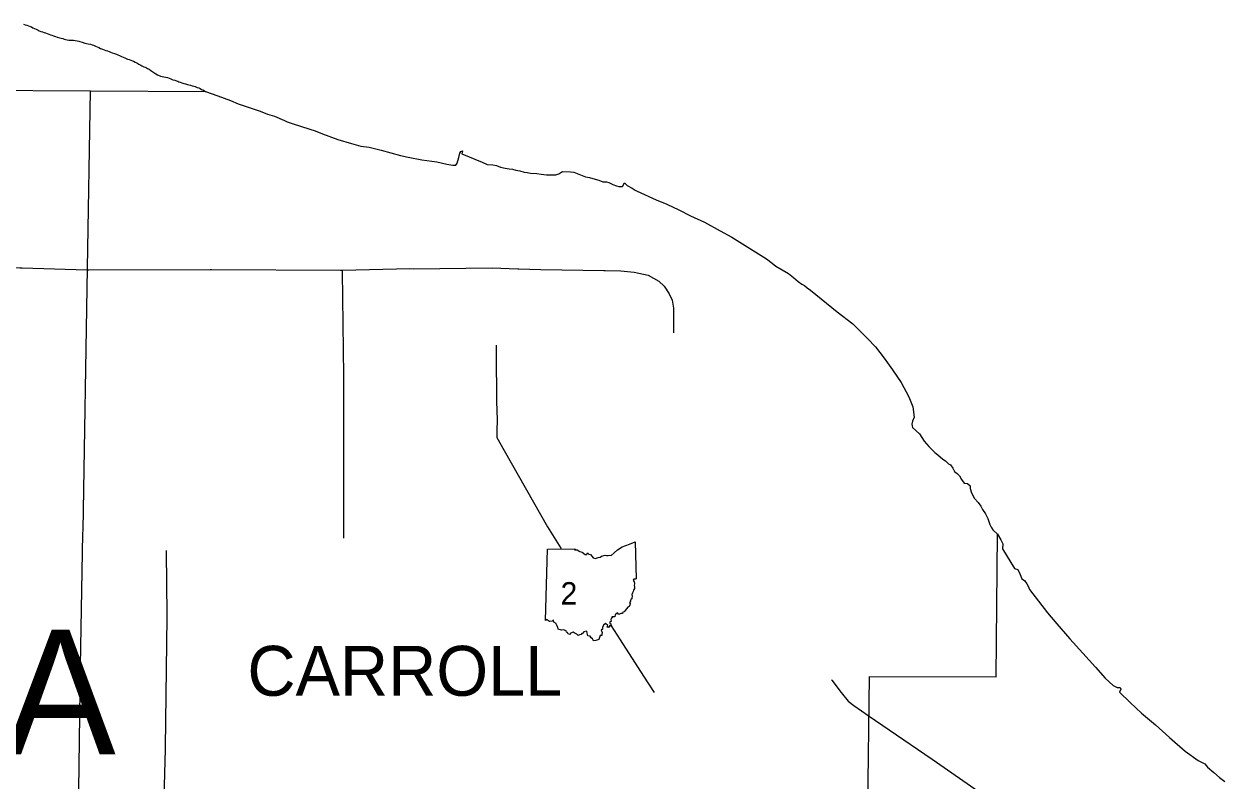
# Model space of a CAD drawing. Extents: x -232 to 448, y 619 to 1059.
# Drawn here: x 271.78 to 321.22, y 890 to 921.13 of the extents above; entities that cross this region are included whole.
import ezdxf

# ---------------------------------------------------------------- set-up
doc = ezdxf.new("R2010")
doc.units = 0
doc.layers.add('Default', color=7, linetype='Continuous')

msp = doc.modelspace()

# ---------------------------------------------------------------- linework, layer by layer
at = {"layer": 'Default'}
msp.add_line((293.244, 896.597), (293.326, 899.525), dxfattribs=at)
msp.add_line((293.244, 896.597), (293.326, 899.525), dxfattribs=at)
for points in [[(271.758, 921.129), (271.835, 921.103), (271.898, 921.082), (271.962, 921.058), (272.035, 921.032), (272.094, 921.008), (272.147, 920.978), (272.218, 920.946), (272.285, 920.92), (272.358, 920.876), (272.411, 920.85), (272.47, 920.829), (272.546, 920.802), (272.613, 920.787), (272.666, 920.767), (272.739, 920.735), (272.8, 920.709), (272.87, 920.686), (272.923, 920.666), (273, 920.642), (273.074, 920.622), (273.147, 920.596), (273.2, 920.579), (273.253, 920.563), (273.318, 920.546), (273.377, 920.528), (273.433, 920.513), (273.496, 920.499), (273.555, 920.48), (273.622, 920.468), (273.694, 920.463), (273.754, 920.462), (273.823, 920.462), (273.891, 920.457), (273.971, 920.441), (274.032, 920.424), (274.085, 920.408), (274.169, 920.382), (274.283, 920.347), (274.356, 920.329), (274.426, 920.314), (274.516, 920.302), (274.587, 920.28), (274.638, 920.257), (274.724, 920.222), (274.789, 920.194), (274.862, 920.16), (274.935, 920.129), (275.013, 920.099), (275.082, 920.071), (275.153, 920.043), (275.216, 920.024), (275.282, 920.002), (275.345, 919.976), (275.414, 919.946), (275.502, 919.918), (275.587, 919.887), (275.644, 919.862), (275.713, 919.831), (275.801, 919.789), (275.87, 919.761), (275.933, 919.739), (275.983, 919.714), (276.039, 919.691), (276.111, 919.672), (276.177, 919.649), (276.25, 919.619), (276.289, 919.596), (276.355, 919.56), (276.428, 919.527), (276.503, 919.474), (276.589, 919.431), (276.638, 919.408), (276.717, 919.375), (276.767, 919.352), (276.819, 919.323), (276.869, 919.303), (276.902, 919.283), (276.931, 919.267), (276.997, 919.214), (277.037, 919.184), (277.205, 919.075)], [(277.205, 919.075), (277.273, 919.039), (277.403, 918.988), (277.475, 918.967), (277.539, 918.962), (277.609, 918.949), (277.684, 918.928), (277.756, 918.898), (277.825, 918.871), (277.911, 918.841), (277.985, 918.818), (278.055, 918.794), (278.108, 918.773), (278.161, 918.754), (278.214, 918.735), (278.284, 918.712), (278.358, 918.688), (278.435, 918.663), (278.505, 918.648), (278.565, 918.631), (278.638, 918.616), (278.704, 918.59), (278.776, 918.571), (278.831, 918.554), (278.909, 918.524), (278.972, 918.499), (279.027, 918.474), (279.084, 918.442), (279.14, 918.417), (279.258, 918.348)], [(241.621, 918.197), (255.575, 918.495), (274.524, 918.377)], [(273.973, 884.01), (273.991, 886.54), (274.111, 894.733), (274.2, 900.175), (274.21, 900.311), (274.401, 911.082), (274.524, 918.377)], [(274.524, 918.377), (279.258, 918.348)], [(279.258, 918.348), (279.753, 918.179), (280.28, 917.98), (280.591, 917.854), (280.921, 917.736), (281.212, 917.643), (281.507, 917.542), (281.808, 917.42), (282.091, 917.334), (282.505, 917.167), (282.619, 917.108), (282.82, 917.045), (283.544, 916.807), (283.763, 916.74), (284.068, 916.608), (284.693, 916.384), (285.261, 916.222), (285.643, 916.111), (285.992, 916.059), (286.48, 915.947), (287.272, 915.728), (287.592, 915.655), (288.159, 915.549), (288.77, 915.456), (289.184, 915.363), (289.435, 915.323), (289.552, 915.329), (289.605, 915.4), (289.68, 915.645), (289.726, 915.821), (289.758, 915.891), (289.833, 915.912), (289.8, 915.789), (290.639, 915.444)], [(290.639, 915.444), (290.85, 915.356), (291.086, 915.332), (291.23, 915.311), (291.398, 915.24), (291.589, 915.196), (291.753, 915.168), (291.895, 915.162), (292.024, 915.122), (292.185, 915.098), (292.365, 915.042), (292.495, 915.017), (292.624, 915), (292.889, 914.98), (293.068, 914.96), (293.286, 914.922), (293.417, 914.93), (293.533, 914.927), (293.676, 914.923), (293.792, 914.963), (293.876, 915.027), (293.944, 915.066), (294.275, 915.056), (294.411, 915.039), (294.887, 914.845), (295.059, 914.813), (295.289, 914.746), (295.448, 914.704), (295.61, 914.636), (295.76, 914.635), (295.858, 914.616), (296.016, 914.527), (296.164, 914.47), (296.271, 914.451), (296.326, 914.447), (296.415, 914.442), (296.504, 914.594), (296.602, 914.483), (296.811, 914.377), (296.94, 914.296), (297.025, 914.252), (297.804, 913.905), (298.243, 913.719), (298.736, 913.484), (299.214, 913.247), (299.786, 912.979), (300.432, 912.622), (300.915, 912.36), (301.46, 912.015), (301.8, 911.808), (302.12, 911.615), (302.348, 911.476), (302.579, 911.289), (302.733, 911.171), (303.246, 910.872), (303.449, 910.701), (303.641, 910.539), (303.795, 910.433), (303.912, 910.379), (304.021, 910.282), (304.16, 910.187), (305.252, 909.296), (305.898, 908.792), (306.504, 908.192), (306.825, 907.857), (307.183, 907.392), (307.528, 906.903), (307.886, 906.39), (308.2, 905.791), (308.373, 905.379), (308.423, 904.954), (308.357, 904.798), (308.329, 904.668), (308.36, 904.539), (308.642, 904.272), (308.832, 903.97), (309.023, 903.757), (309.272, 903.507), (309.395, 903.407), (309.598, 903.233), (309.709, 903.167), (309.779, 903.095), (309.838, 903.045), (309.922, 902.997), (310.012, 902.867), (310.087, 902.72), (310.194, 902.646), (310.288, 902.542), (310.368, 902.396), (310.486, 902.239), (310.614, 902.234), (310.731, 902.137), (310.724, 902.03), (310.779, 901.852), (310.903, 901.609), (311.059, 901.447), (311.163, 901.305), (311.237, 901.166), (311.355, 900.978), (311.455, 900.788), (311.53, 900.541)], [(263.548, 911.236), (268.802, 911.127), (268.896, 911.125), (271.605, 911.101), (271.711, 911.1), (274.364, 911.019), (274.454, 911.016), (279.438, 911.028), (279.505, 911.028), (284.814, 911.012), (284.814, 911.012), (284.826, 911.012)], [(284.826, 911.012), (284.886, 911.012), (287.657, 911.071), (287.815, 911.065), (291.047, 911.098), (292.102, 911.066)], [(292.102, 911.066), (292.156, 911.064)], [(292.156, 911.064), (293.055, 911.037), (294.784, 911.004), (295.65, 910.995), (295.706, 910.995)], [(284.945, 902.04), (284.946, 906.577), (284.946, 906.664), (284.888, 910.943), (284.888, 910.943), (284.886, 911.012)], [(295.706, 910.995), (296.348, 910.983), (296.899, 910.919), (297.475, 910.802), (297.911, 910.557), (298.125, 910.345), (298.337, 910.034), (298.464, 909.77), (298.512, 909.437), (298.52, 908.477), (298.52, 908.432)], [(291.219, 907.916), (291.22, 907.581), (291.232, 905.619), (291.258, 904.84), (291.245, 904.416), (291.245, 904.128), (291.544, 903.59), (293.334, 900.444), (293.874, 899.568), (293.894, 899.535)], [(284.944, 899.986), (284.944, 900.022), (284.945, 902.04)], [(311.53, 900.541), (311.593, 900.436), (311.661, 900.32), (311.845, 900.143)], [(293.326, 899.525), (294.462, 899.545), (294.444, 899.509), (294.552, 899.502), (294.665, 899.439), (294.762, 899.4), (294.88, 899.307), (294.95, 899.308), (294.98, 899.384), (295.034, 899.325), (295.098, 899.314), (295.209, 899.174), (295.3, 899.144), (295.41, 899.192), (295.492, 899.2), (295.551, 899.247), (295.707, 899.288), (295.751, 899.264), (295.833, 899.269), (295.875, 899.287), (295.947, 899.27), (296.074, 899.377), (296.204, 899.503), (296.405, 899.621), (296.705, 899.733), (296.942, 899.834), (296.976, 898.314)], [(293.326, 899.525), (294.462, 899.545), (294.444, 899.509), (294.552, 899.502), (294.665, 899.439), (294.762, 899.4), (294.88, 899.307), (294.95, 899.308), (294.98, 899.384), (295.034, 899.325), (295.098, 899.314), (295.209, 899.174), (295.3, 899.144), (295.41, 899.192), (295.492, 899.2), (295.551, 899.247), (295.707, 899.288), (295.751, 899.264), (295.833, 899.269), (295.875, 899.287), (295.947, 899.27), (296.074, 899.377), (296.204, 899.503), (296.405, 899.621), (296.705, 899.733), (296.942, 899.834), (296.976, 898.314)], [(306.452, 883.484), (306.59, 894.29), (311.799, 894.273), (311.845, 900.143)], [(311.845, 900.143), (311.99, 899.915), (312.068, 899.754), (312.054, 899.548), (312.555, 898.738), (312.682, 898.697), (312.784, 898.494), (312.855, 898.311), (312.968, 898.236), (313.066, 898.104), (313.111, 898.013), (313.166, 897.877), (313.914, 896.905), (314.297, 896.461), (314.825, 895.845), (315.363, 895.247), (315.883, 894.676), (316.284, 894.223), (316.608, 893.925), (316.778, 893.834), (316.901, 893.833), (316.93, 893.765), (316.87, 893.654), (317.316, 893.22), (317.781, 892.779), (318.359, 892.3), (318.93, 891.785), (319.578, 891.218), (320.109, 890.84), (320.388, 890.699), (320.496, 890.567), (320.758, 890.349), (320.986, 890.144), (321.215, 889.978)], [(277.536, 888.796), (277.606, 891.306), (277.607, 891.375), (277.67, 896.738), (277.671, 896.823), (277.644, 899.424), (277.643, 899.47)], [(296.976, 898.314), (296.941, 898.292), (296.887, 898.302), (296.85, 898.26), (296.895, 898.189), (296.917, 898.114), (296.898, 898.031), (296.916, 897.962), (296.904, 897.905), (296.869, 897.848), (296.858, 897.794), (296.829, 897.737), (296.831, 897.705), (296.803, 897.68), (296.808, 897.584), (296.794, 897.532), (296.799, 897.486), (296.754, 897.474), (296.764, 897.437), (296.736, 897.408), (296.742, 897.358), (296.709, 897.326), (296.741, 897.262), (296.716, 897.242), (296.695, 897.165), (296.637, 897.149), (296.521, 897.007), (296.481, 896.953), (296.435, 896.94), (296.41, 896.885), (296.353, 896.885), (296.268, 896.847), (296.213, 896.912), (296.116, 896.833), (296.105, 896.742), (295.982, 896.745), (295.987, 896.699), (295.96, 896.685), (295.935, 896.639), (295.95, 896.557), (295.892, 896.536), (295.899, 896.488), (295.936, 896.459), (295.952, 896.368), (295.891, 896.386), (295.842, 896.309), (295.79, 896.327), (295.807, 896.392), (295.721, 896.471), (295.639, 896.408), (295.596, 896.308), (295.595, 896.24), (295.534, 896.2), (295.574, 896.104), (295.566, 896.039), (295.568, 895.977), (295.491, 895.979), (295.445, 895.811)], [(296.976, 898.314), (296.941, 898.292), (296.887, 898.302), (296.85, 898.26), (296.895, 898.189), (296.917, 898.114), (296.898, 898.031), (296.916, 897.962), (296.904, 897.905), (296.869, 897.848), (296.858, 897.794), (296.829, 897.737), (296.831, 897.705), (296.803, 897.68), (296.808, 897.584), (296.794, 897.532), (296.799, 897.486), (296.754, 897.474), (296.764, 897.437), (296.736, 897.408), (296.742, 897.358), (296.709, 897.326), (296.741, 897.262), (296.716, 897.242), (296.695, 897.165), (296.637, 897.149), (296.521, 897.007), (296.481, 896.953), (296.435, 896.94), (296.41, 896.885), (296.353, 896.885), (296.268, 896.847), (296.213, 896.912), (296.116, 896.833), (296.105, 896.742), (295.982, 896.745), (295.987, 896.699), (295.96, 896.685), (295.935, 896.639), (295.95, 896.557), (295.892, 896.536), (295.899, 896.488), (295.936, 896.459), (295.952, 896.368), (295.891, 896.386), (295.842, 896.309), (295.79, 896.327), (295.807, 896.392), (295.721, 896.471), (295.639, 896.408), (295.596, 896.308), (295.595, 896.24), (295.534, 896.2), (295.574, 896.104), (295.566, 896.039), (295.568, 895.977), (295.491, 895.979), (295.445, 895.811)], [(295.445, 895.811), (295.312, 895.778), (295.22, 895.759), (295.188, 895.836), (295.122, 895.876), (295.079, 895.953), (294.985, 895.963), (294.962, 896.069), (294.952, 896.155), (294.823, 896.133), (294.787, 896.081), (294.741, 896.067), (294.715, 896.014), (294.652, 896.01), (294.585, 895.985), (294.541, 896.037), (294.431, 896.089), (294.382, 896.115), (294.279, 896.074), (294.257, 896.024), (294.174, 896.046), (294.155, 896.101), (294.105, 896.118), (294.094, 896.176), (293.988, 896.207), (293.907, 896.195), (293.763, 896.242), (293.755, 896.318), (293.706, 896.412), (293.68, 896.477), (293.589, 896.526), (293.571, 896.604), (293.542, 896.601), (293.516, 896.57), (293.415, 896.556), (293.375, 896.587), (293.318, 896.641), (293.244, 896.597)], [(295.445, 895.811), (295.312, 895.778), (295.22, 895.759), (295.188, 895.836), (295.122, 895.876), (295.079, 895.953), (294.985, 895.963), (294.962, 896.069), (294.952, 896.155), (294.823, 896.133), (294.787, 896.081), (294.741, 896.067), (294.715, 896.014), (294.652, 896.01), (294.585, 895.985), (294.541, 896.037), (294.431, 896.089), (294.382, 896.115), (294.279, 896.074), (294.257, 896.024), (294.174, 896.046), (294.155, 896.101), (294.105, 896.118), (294.094, 896.176), (293.988, 896.207), (293.907, 896.195), (293.763, 896.242), (293.755, 896.318), (293.706, 896.412), (293.68, 896.477), (293.589, 896.526), (293.571, 896.604), (293.542, 896.601), (293.516, 896.57), (293.415, 896.556), (293.375, 896.587), (293.318, 896.641), (293.244, 896.597)], [(295.944, 896.37), (296.317, 895.802), (297.278, 894.311), (297.719, 893.637)], [(305.021, 894.154), (305.03, 894.14), (305.421, 893.632), (305.701, 893.274), (305.944, 893.1)], [(305.944, 893.1), (306.564, 892.658), (307.395, 892.092), (309.168, 890.891), (311.867, 889.017), (312.099, 888.877), (312.84, 888.428), (313.511, 888.022)]]:
    msp.add_lwpolyline(points, dxfattribs=at)

# ---------------------------------------------------------------- texts
for s, height, p in [(' 2 ', 0.9234, (293.526, 897.25)), ('OTTAWA', 5.13, (246.217, 891.091)), ('CARROLL', 2.052, (280.977, 893.5))]:
    msp.add_text(s, height=height, dxfattribs=at).set_placement(p)

doc.saveas('drawing.dxf')
